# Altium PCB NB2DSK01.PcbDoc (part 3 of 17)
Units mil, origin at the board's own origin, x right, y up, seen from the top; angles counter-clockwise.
Board outline 11815 x 6500.03 mil, 8 copper layers (Top Layer, MidLayer1, MidLayer2, GND, PWR, MidLayer3, MidLayer4, Bottom Layer), stack 74.62 mil thick; 798 components, 1002 nets, 3927 pads, 3182 vias.
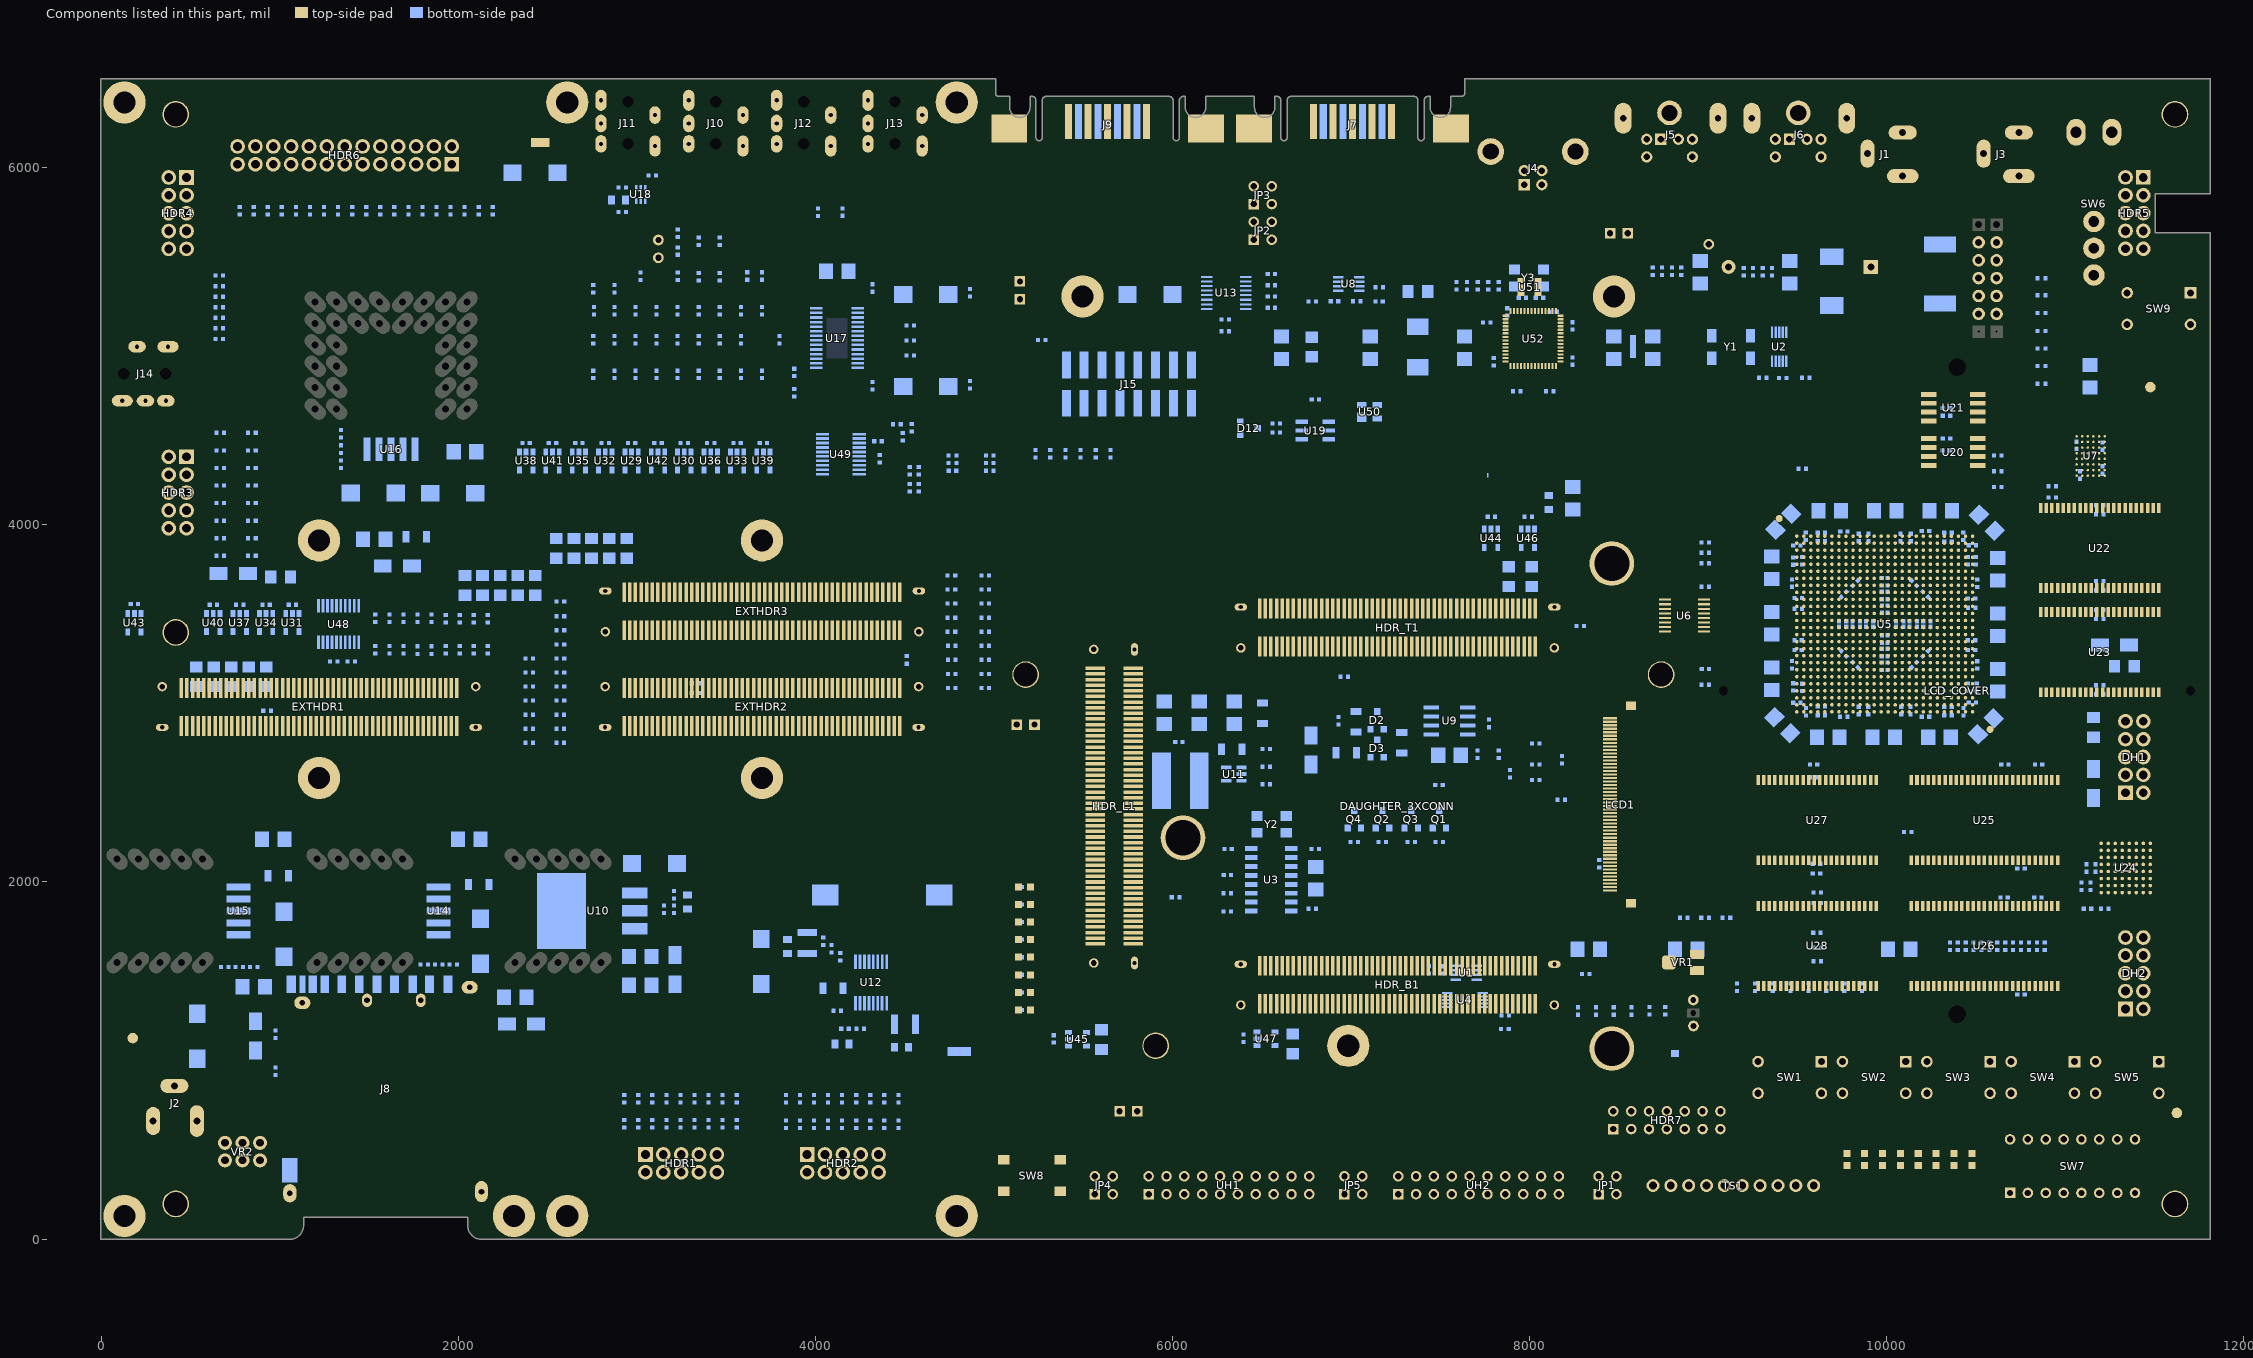
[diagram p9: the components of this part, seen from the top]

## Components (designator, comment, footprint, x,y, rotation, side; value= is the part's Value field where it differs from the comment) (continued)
R303 "1K 1%" RESC1005-STAR 10866.58,5086 r0 bottom locked (schematic designator R12)
R304 "4K7 1%" RESC1005-STAR 10866.58,4987.57 r0 bottom locked (schematic designator R8)
R305 "100R 1%" RESC1005-STAR 10866.58,5381.27 r180 bottom locked (schematic designator R9)
R306 "100R 1%" RESC1005-STAR 10866.58,5286 r180 bottom locked (schematic designator R10)
R307 "100R 1%" RESC1005-STAR 10866.58,4889.15 r0 bottom locked (schematic designator R11)
R308 "100R 1%" RESC1005-STAR 10866.58,4790.72 r0 bottom locked (schematic designator R13)
R309 "1K 1%" RESC1005-STAR 10866.58,5186 r180 bottom locked (schematic designator R14)
R311 "2K7 1%" RESC1005-STAR 7649.66,5338.57 r90 bottom (schematic designator R1_US)
R312 "5K6 1%" RESC1005-STAR 7590.54,5338.57 r270 bottom (schematic designator R2_US)
R313 "10K 1%" RESC1005-STAR 7827.02,5338.57 r270 bottom (schematic designator R8_US)
R314 "4K7 1%" RESC1005-STAR 8112.2,4748.03 r0 bottom locked (schematic designator R4_US)
R315 "27R 1%" RESC1005-STAR 9527.54,4314.95 r180 bottom locked (schematic designator R3_US)
R316 "4K7 1%" RESC1005-STAR 7927.17,4748.03 r180 bottom locked (schematic designator R7_US)
R317 "10M 1%" RESC3216 7373.87,5307.09 r180 bottom (schematic designator R9_US)
R318 "4K7 1%" RESC1005-STAR 7767.9,5338.57 r270 bottom (schematic designator R5_US)
R319 "4K7 1%" RESC1005-STAR 7708.78,5338.57 r270 bottom (schematic designator R6_US)
R320 "120R 1%" RESC1005-STAR 5231.88,4398.03 r270 bottom (schematic designator R3)
SW1 "DPNO TACTILE" IT-2175#1 9456.69,905.51 r180 top locked
SW2 "DPNO TACTILE" IT-2175#1 9929.13,905.51 r180 top locked
SW3 "DPNO TACTILE" IT-2175#1 10401.57,905.51 r180 top locked
SW4 "DPNO TACTILE" IT-2175#1 10874.02,905.51 r180 top locked
SW5 "DPNO TACTILE" IT-2175#1 11346.46,905.51 r180 top locked
SW6 "SPDT SUB" T8019L-TNQ 11160.24,6492.13 r180 top locked (schematic designator SW8)
SW7 "DIP-16 8-way Switch" DIP-16-KEY 10690.32,258.43 r0 top locked (schematic designator SW1)
SW8 "SPNO" SW_DTSM-61NT/R 5212.6,356.3 r0 top locked (schematic designator SW1)
SW9 "DPNO TACTILE" IT-2175#2 11523.62,5211.09 r180 top (schematic designator SW1)
TP1 "5V0" TestPin#1 10614.94,5381.97 r0 top (schematic designator TP2)
TP2 "32K768HZ" TestPin#2 9003.27,5571.82 r180 top locked (schematic designator TP1)
TP3 "REF CLK" TestPin#3 8917.31,1193.48 r180 top (schematic designator TP1)
TP4 "FPGA CLK" TestPin#3 8916.9,1339.03 r180 top (schematic designator TP2)
TP5 "-7V5" TestPin#1 10514.94,5581.97 r180 top (schematic designator TP1)
TP6 "9V0" TestPin#1 10514.94,5381.97 r180 top (schematic designator TP1)
TP7 "VCCX" TestPin#1 10614.94,5581.97 r0 top (schematic designator TP1)
TP8 "16V5" TestPin#1 10514.94,5481.97 r180 top (schematic designator TP1)
TP9 "1V2" TestPin#1 10614.94,5481.97 r0 top (schematic designator TP1)
TP10 "1V8" TestPin#1 10614.94,5281.97 r0 top (schematic designator TP1)
TP11 "2V5" TestPin#1 10514.94,5281.97 r180 top (schematic designator TP1)
TP12 "3V3" TestPin#1 10514.94,5181.97 r180 top (schematic designator TP1)
TP13 "MIXER LEFT" TestPin#2 3120.73,5495.67 r180 top locked (schematic designator TP1)
TP14 "MIXER RIGHT" TestPin#2 3120.73,5595.67 r180 top locked (schematic designator TP2)
TP15 "VBATT" TestPin#1 10614.94,5181.97 r0 top
TS1 "TERMINAL 10 HEADER" TS2.54X10 8690.67,300 r90 top locked
U1 "MAX1037EKA-T" SOT65P280-8 7645.59,1492.06 r180 bottom
U2 "DS1391U-33" SSOP50P490-10 9397.66,4997.47 r0 bottom locked (schematic designator U5)
U3 "ICS307-02" SOIC127P600-16 6553.15,2012.01 r270 bottom locked (schematic designator U1)
U4 "MAX5841MEUB" TSSOP50P490-10 7637.8,1339.38 r0 bottom (schematic designator U1)
U5 "XC3S1500-4FG676C" BGA100P26X26-676 9988.19,3444.88 r0 top locked (schematic designator U1)
U6 "AD7843ARU" TSOP65P638-16 8867.13,3491.5 r270 top locked (schematic designator U15)
U7 "XCF08PFS48C" BGA80P8X6-48 11141.73,4385.83 r270 top locked (schematic designator U1)
U8 "MAX3051EKA-T" SOT65P280-8 6986.05,5349.48 r180 bottom locked (schematic designator U1)
U9 "VRG-100mA-1.2V-37V-4%-75102" SOP127P600-8 7551.18,2901.77 r270 bottom locked (schematic designator U1)
U10 "LM1084IS-ADJ" TO254P1435-4 2988.68,1938.45 r270 bottom (schematic designator U1)
U11 "LM2704MF-ADJCT-ND" SOT95P284-5 6343.5,2604.33 r270 bottom locked (schematic designator U1)
U12 "MAX1831EEE" SOP63P602-16 4311.68,1437.45 r90 bottom (schematic designator U1)
U13 "MAX3232EUE" TSOP65P638-16 6301.84,5299.21 r270 bottom locked (schematic designator U9)
U14 "TPS75501KTTT" TO-263 1888.68,1838.45 r270 bottom (schematic designator U1)
U15 "TPS75501KTTT" TO-263 768.68,1838.45 r270 bottom (schematic designator U1)
U16 "TPS75501KTTT" TO-263 1623.68,4423.45 r180 bottom (schematic designator U1)
U17 "LM4849MH" TSOP65P640_HS-28 4003.94,4879.92 r90 bottom (schematic designator U1)
U18 "MAX9812L" SC70_6L 3047.24,5814.96 r180 bottom (schematic designator U1MIC)
U19 "DS2406" TSOC6 6799.27,4528.53 r270 bottom (schematic designator U1_NB)
U20 "M25P80-VMW6 8Mbit Serial Flash" SOIC8-200-BODY 10234.25,4483.07 r270 top locked (schematic designator U1)
U21 "M25P80-VMW6 8Mbit Serial Flash" SOIC8-200-BODY 10234.25,4731.1 r270 top locked (schematic designator U2)
U22 "SRAM-256Kx16" TSOP80P1176-44 11192.91,3870.08 r0 top locked (schematic designator U1)
U23 "SRAM-256Kx16" TSOP80P1176-44 11192.91,3287.4 r0 top locked (schematic designator U2)
U24 "S29GL256N11FFIV10" BGA100P8X8-64 11338.58,2078.56 r270 top locked (schematic designator U1)
U25 "SDRAM-16Mx16" TSOP80P1176-54 10547.25,2346.46 r180 top locked (schematic designator U1)
U26 "SDRAM-16Mx16" TSOP80P1176-54 10547.25,1641.73 r180 top locked (schematic designator U2)
U27 "SRAM-256Kx16" TSOP80P1176-44 9610.24,2346.46 r180 top locked (schematic designator U1)
U28 "SRAM-256Kx16" TSOP80P1176-44 9610.24,1641.73 r180 top locked (schematic designator U2)
U29 "MAX4372" SOT-23-5 2933.07,4409.45 r0 bottom (schematic designator U8)
U30 "MAX4372" SOT-23-5 3228.35,4409.45 r0 bottom (schematic designator U15)
U31 "MAX4372" SOT-23-5 1033.46,3503.94 r0 bottom (schematic designator U1)
U32 "MAX4372" SOT-23-5 2785.43,4409.45 r0 bottom (schematic designator U9)
U33 "MAX4372" SOT-23-5 3523.62,4409.45 r0 bottom (schematic designator U16)
U34 "MAX4372" SOT-23-5 885.83,3503.94 r0 bottom (schematic designator U2)
U35 "MAX4372" SOT-23-5 2637.8,4409.45 r0 bottom (schematic designator U10)
U36 "MAX4372" SOT-23-5 3375.98,4409.45 r0 bottom (schematic designator U17)
U37 "MAX4372" SOT-23-5 738.19,3503.94 r0 bottom (schematic designator U3)
U38 "MAX4372" SOT-23-5 2342.52,4409.45 r0 bottom (schematic designator U11)
U39 "MAX4372" SOT-23-5 3671.26,4409.45 r0 bottom (schematic designator U18)
U40 "MAX4372" SOT-23-5 590.55,3503.94 r0 bottom (schematic designator U4)
U41 "MAX4372" SOT-23-5 2490.16,4409.45 r0 bottom (schematic designator U12)
U42 "MAX4372" SOT-23-5 3080.71,4409.45 r0 bottom (schematic designator U19)
U43 "MAX4372" SOT-23-5 148.61,3502.9 r0 bottom (schematic designator U5)
U44 "MAX4372" SOT-23-5 7746.06,3976.38 r0 bottom (schematic designator U6)
U45 "MAX4372" SOT-23-5 5417.41,1082.08 r90 bottom (schematic designator U20)
U46 "MAX4372" SOT-23-5 7952.76,3976.38 r0 bottom (schematic designator U7)
U47 "MAX4372" SOT-23-5 6473,1085.1 r90 bottom (schematic designator U21)
U48 "MAX1229" QSOP65P600-20 1217.5,3547.24 r0 bottom (schematic designator U13)
U49 "MAX1229" QSOP65P600-20 4039.37,4283.46 r90 bottom (schematic designator U14)
U50 "MAX6315US26D1" SOT143 7103.55,4633.53 r90 bottom locked (schematic designator U16_US)
U51 "NUP2201MR6T1G" TSOP95P275-6 8000,5331.69 r90 top (schematic designator U13_US)
U52 "CY7C68001-56LFC" QFN50P800X800_HS-57 8019.68,5043.45 r180 top (schematic designator U7_US)
UH1 "2x10 HEADER" HDR2X10 5866.14,251.97 r0 top locked
UH2 "2x10 HEADER" HDR2X10 7263.78,251.97 r0 top locked
VR1 "20K linear" TRIM_3314J-1-203E 8858.27,1549.47 r180 top
VR2 "2x5K linear" POT-R0911G-A1 791.34,539.37 r180 bottom locked (schematic designator VR1)
Y1 "32.768 kHz 12.5pF" "XTAL QSC26 QSMC-200S COMBI" 9276.27,4996.46 r90 bottom
Y2 "20MHZ" XTAL-200X126-4 6555.12,2322.84 r180 bottom locked (schematic designator Y1)
Y3 "24MHZ" XTAL-200X126-4 7996.06,5382.69 r180 bottom (schematic designator Y1_US)

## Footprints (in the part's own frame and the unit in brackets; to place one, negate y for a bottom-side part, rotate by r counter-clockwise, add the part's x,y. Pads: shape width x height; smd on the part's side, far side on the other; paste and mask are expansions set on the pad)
0603LED [mm]
  rect 1x1 smd paste+0 mask+0: 1(0.85,0) 2(-0.85,0)
  silkscreen extent -1.97,-0.85 1.6,0.85, body extent -0.92,-0.53 1.09,0.53, height 0.46
53751 [mm]
  rect 0.5x2.8 smd: 1(-19.6,-2.7) 2(-19.6,2.7) 3(-18.8,-2.7) 4(-18.8,2.7) 5(-18,-2.7) 6(-18,2.7) 7(-17.2,-2.7) 8(-17.2,2.7) 9(-16.4,-2.7) 10(-16.4,2.7) 11(-15.6,-2.7) 12(-15.6,2.7) 13(-14.8,-2.7) 14(-14.8,2.7) 15(-14,-2.7) 16(-14,2.7) 17(-13.2,-2.7) 18(-13.2,2.7) 19(-12.4,-2.7) 20(-12.4,2.7) 21(-11.6,-2.7) 22(-11.6,2.7) 23(-10.8,-2.7) 24(-10.8,2.7) 25(-10,-2.7) 26(-10,2.7) 27(-9.2,-2.7) 28(-9.2,2.7) 29(-8.4,-2.7) 30(-8.4,2.7) 31(-7.6,-2.7) 32(-7.6,2.7) 33(-6.8,-2.7) 34(-6.8,2.7) 35(-6,-2.7) 36(-6,2.7) 37(-5.2,-2.7) 38(-5.2,2.7) 39(-4.4,-2.7) 40(-4.4,2.7) 41(-3.6,-2.7) 42(-3.6,2.7) 43(-2.8,-2.7) 44(-2.8,2.7) 45(-2,-2.7) 46(-2,2.7) 47(-1.2,-2.7) 48(-1.2,2.7) 49(-0.4,-2.7) 50(-0.4,2.7) 51(0.4,-2.7) 52(0.4,2.7) 53(1.2,-2.7) 54(1.2,2.7) 55(2,-2.7) 56(2,2.7) 57(2.8,-2.7) 58(2.8,2.7) 59(3.6,-2.7) 60(3.6,2.7) 61(4.4,-2.7) 62(4.4,2.7) 63(5.2,-2.7) 64(5.2,2.7) 65(6,-2.7) 66(6,2.7) 67(6.8,-2.7) 68(6.8,2.7) 69(7.6,-2.7) 70(7.6,2.7) 71(8.4,-2.7) 72(8.4,2.7) 73(9.2,-2.7) 74(9.2,2.7) 75(10,-2.7) 76(10,2.7) 77(10.8,-2.7) 78(10.8,2.7) 79(11.6,-2.7) 80(11.6,2.7) 81(12.4,-2.7) 82(12.4,2.7) 83(13.2,-2.7) 84(13.2,2.7) 85(14,-2.7) 86(14,2.7) 87(14.8,-2.7) 88(14.8,2.7) 89(15.6,-2.7) 90(15.6,2.7) 91(16.4,-2.7) 92(16.4,2.7) 93(17.2,-2.7) 94(17.2,2.7) 95(18,-2.7) 96(18,2.7) 97(18.8,-2.7) 98(18.8,2.7) 99(19.6,-2.7) 100(19.6,2.7)
  round 1.35 hole 0.8: MH1(-22.283,-2.9) MH3(22.317,-2.9)
  oval 1.8x1 hole 0.6 slot 1.4 at 0 deg: MH2(-22.283,2.9) MH4(22.317,2.9)
  silkscreen extent -30,-4.77 30.05,4.5, body extent -30.33,-4.4 30.37,4.4, height 11.7
070221XE009GX14BU#1 [mm]
  rect 1x5 smd mask+0: 1(5.55,0) 2(2.775,0) 3(0,0) 4(-2.775,0) 5(-5.55,0)
  rect 1x5 smd far side mask+0: 6(4.163,0) 7(1.388,0) 8(-1.388,0) 9(-4.163,0)
  rect 5.08x4 smd mask+0: 10(14,-1) 11(-14,-1)
  silkscreen extent -16.5,-4.9 16.5,8.01, body extent -15.41,-0.4 15.41,14.1, height 6.25
070221XE009GX14BU#2 [mm]
  rect 1x5 smd mask+0: 1(5.55,0) 2(2.775,0) 3(0,0) 4(-2.775,0) 5(-5.55,0)
  rect 1x5 smd far side: 6(4.163,0) 7(1.388,0) 8(-1.388,0) 9(-4.163,0)
  rect 5.08x4 smd mask+0.051: 10(14,-1) 11(-14,-1)
  silkscreen extent -16.5,-4.9 16.5,8.01, body extent -15.41,-0.4 15.41,14.1, height 6.25
440119 [mm] "Connector; USB1.1, Type B, Thru-Hole; 4 Position; Right Angle"
  rect 1.6x1.6 hole 0.9: 1(-1,1.25)
  round 1.6 hole 0.9: 2(-1,-1.25) 3(1,-1.25) 4(1,1.25)
  round 3.8 hole 2.3: 5(3.71,6.02) 6(3.71,-6.02)
  silkscreen extent -2.41,-8.25 13.99,8.24, body extent -1.44,-6.75 13.28,8.15, height 8.15
918510X323#1 [mil] "Connector; IDC, Low Profile Male Header, Thru-Hole; 10 Position; Right Angle; Pitch 2.54 mm; Body 20.32 x 8.9 x 9.2 mm (LxWxH)"
  rect 82x82 hole 49.21: 1(-200,-100)
  round 82 hole 49.21: 2(-200,0) 3(-100,-100) 4(-100,0) 5(0,-100) 6(0,0) 7(100,-100) 8(100,0) 9(200,-100) 10(200,0)
  silkscreen extent -400,0 400,372, body extent -406,-123 406,374, height 315
918510X323#2 [mil] "Connector; IDC, Low Profile Male Header, Thru-Hole; 10 Position; Right Angle; Pitch 2.54 mm; Body 20.32 x 8.9 x 9.2 mm (LxWxH)"
  rect 82x82 hole 49.21: 1(200,100)
  round 82 hole 49.21: 2(200,0) 3(100,100) 4(100,0) 5(0,100) 6(0,0) 7(-100,100) 8(-100,0) 9(-200,100) 10(-200,0)
  silkscreen extent -400,-372 400,0
918510X323#3 [mil] "Connector; IDC, Low Profile Male Header, Thru-Hole; 10 Position; Right Angle; Pitch 2.54 mm; Body 20.32 x 8.9 x 9.2 mm (LxWxH)"
  rect 82x82 hole 49.21: 1(200,0)
  round 82 hole 49.21: 2(200,-100) 3(100,0) 4(100,-100) 5(0,0) 6(0,-100) 7(-100,0) 8(-100,-100) 9(-200,0) 10(-200,-100)
  silkscreen extent -400,0 400,372, body extent -406,-123 406,374, height 315
BGA80P8X6-48 [mm] "48-Ball Chip Scale Ball Grid Array 0.8mm Pitch (FS48)"
  round 0.35 smd: A1(-2.8,-2) A2(-2.8,-1.2) A3(-2.8,-0.4) A4(-2.8,0.4) A5(-2.8,1.2) A6(-2.8,2) B1(-2,-2) B2(-2,-1.2) B3(-2,-0.4) B4(-2,0.4) B5(-2,1.2) B6(-2,2) C1(-1.2,-2) C2(-1.2,-1.2) C3(-1.2,-0.4) C4(-1.2,0.4) C5(-1.2,1.2) C6(-1.2,2) D1(-0.4,-2) D2(-0.4,-1.2) D3(-0.4,-0.4) D4(-0.4,0.4) D5(-0.4,1.2) D6(-0.4,2) E1(0.4,-2) E2(0.4,-1.2) E3(0.4,-0.4) E4(0.4,0.4) E5(0.4,1.2) E6(0.4,2) F1(1.2,-2) F2(1.2,-1.2) F3(1.2,-0.4) F4(1.2,0.4) F5(1.2,1.2) F6(1.2,2) G1(2,-2) G2(2,-1.2) G3(2,-0.4) G4(2,0.4) G5(2,1.2) G6(2,2) H1(2.8,-2) H2(2.8,-1.2) H3(2.8,-0.4) H4(2.8,0.4) H5(2.8,1.2) H6(2.8,2)
  silkscreen extent -4.5,-4.78 4.5,4, body extent -4.51,-3.92 4.42,3.97, height 1
BGA100P8X8-64 [mm] "AMD 64-Ball Fortfied Ball grid Array (FBGA)"
  round 0.5 smd: A1(-3.5,-3.5) A2(-3.5,-2.5) A3(-3.5,-1.5) A4(-3.5,-0.5) A5(-3.5,0.5) A6(-3.5,1.5) A7(-3.5,2.5) A8(-3.5,3.5) B1(-2.5,-3.5) B2(-2.5,-2.5) B3(-2.5,-1.5) B4(-2.5,-0.5) B5(-2.5,0.5) B6(-2.5,1.5) B7(-2.5,2.5) B8(-2.5,3.5) C1(-1.5,-3.5) C2(-1.5,-2.5) C3(-1.5,-1.5) C4(-1.5,-0.5) C5(-1.5,0.5) C6(-1.5,1.5) C7(-1.5,2.5) C8(-1.5,3.5) D1(-0.5,-3.5) D2(-0.5,-2.5) D3(-0.5,-1.5) D4(-0.5,-0.5) D5(-0.5,0.5) D6(-0.5,1.5) D7(-0.5,2.5) D8(-0.5,3.5) E1(0.5,-3.5) E2(0.5,-2.5) E3(0.5,-1.5) E4(0.5,-0.5) E5(0.5,0.5) E6(0.5,1.5) E7(0.5,2.5) E8(0.5,3.5) F1(1.5,-3.5) F2(1.5,-2.5) F3(1.5,-1.5) F4(1.5,-0.5) F5(1.5,0.5) F6(1.5,1.5) F7(1.5,2.5) F8(1.5,3.5) G1(2.5,-3.5) G2(2.5,-2.5) G3(2.5,-1.5) G4(2.5,-0.5) G5(2.5,0.5) G6(2.5,1.5) G7(2.5,2.5) G8(2.5,3.5) H1(3.5,-3.5) H2(3.5,-2.5) H3(3.5,-1.5) H4(3.5,-0.5) H5(3.5,0.5) H6(3.5,1.5) H7(3.5,2.5) H8(3.5,3.5)
  silkscreen extent -6.5,-6.32 6.5,5.5, body extent -6.35,-5.4 6.41,5.36, height 1
BGA100P26X26-676 [mm]
  round 0.5 smd: A1(-12.5,12.5) A2(-11.5,12.5) A3(-10.5,12.5) A4(-9.5,12.5) A5(-8.5,12.5) A6(-7.5,12.5) A7(-6.5,12.5) A8(-5.5,12.5) A9(-4.5,12.5) A10(-3.5,12.5) A11(-2.5,12.5) A12(-1.5,12.5) A13(-0.5,12.5) A14(0.5,12.5) A15(1.5,12.5) A16(2.5,12.5) A17(3.5,12.5) A18(4.5,12.5) A19(5.5,12.5) A20(6.5,12.5) A21(7.5,12.5) A22(8.5,12.5) A23(9.5,12.5) A24(10.5,12.5) A25(11.5,12.5) A26(12.5,12.5) AA1(-12.5,-7.5) AA2(-11.5,-7.5) AA3(-10.5,-7.5) AA4(-9.5,-7.5) AA5(-8.5,-7.5) AA6(-7.5,-7.5) AA7(-6.5,-7.5) AA8(-5.5,-7.5) AA9(-4.5,-7.5) AA10(-3.5,-7.5) AA11(-2.5,-7.5) AA12(-1.5,-7.5) AA13(-0.5,-7.5) AA14(0.5,-7.5) AA15(1.5,-7.5) AA16(2.5,-7.5) AA17(3.5,-7.5) AA18(4.5,-7.5) AA19(5.5,-7.5) AA20(6.5,-7.5) AA21(7.5,-7.5) AA22(8.5,-7.5) AA23(9.5,-7.5) AA24(10.5,-7.5) AA25(11.5,-7.5) AA26(12.5,-7.5) AB1(-12.5,-8.5) AB2(-11.5,-8.5) AB3(-10.5,-8.5) AB4(-9.5,-8.5) AB5(-8.5,-8.5) AB6(-7.5,-8.5) AB7(-6.5,-8.5) AB8(-5.5,-8.5) AB9(-4.5,-8.5) AB10(-3.5,-8.5) AB11(-2.5,-8.5) AB12(-1.5,-8.5) AB13(-0.5,-8.5) AB14(0.5,-8.5) AB15(1.5,-8.5) AB16(2.5,-8.5) AB17(3.5,-8.5) AB18(4.5,-8.5) AB19(5.5,-8.5) AB20(6.5,-8.5) AB21(7.5,-8.5) AB22(8.5,-8.5) AB23(9.5,-8.5) AB24(10.5,-8.5) AB25(11.5,-8.5) AB26(12.5,-8.5) AC1(-12.5,-9.5) AC2(-11.5,-9.5) AC3(-10.5,-9.5) AC4(-9.5,-9.5) AC5(-8.5,-9.5) AC6(-7.5,-9.5) AC7(-6.5,-9.5) AC8(-5.5,-9.5) AC9(-4.5,-9.5) AC10(-3.5,-9.5) AC11(-2.5,-9.5) AC12(-1.5,-9.5) AC13(-0.5,-9.5) AC14(0.5,-9.5) AC15(1.5,-9.5) AC16(2.5,-9.5) AC17(3.5,-9.5) AC18(4.5,-9.5) AC19(5.5,-9.5) AC20(6.5,-9.5) AC21(7.5,-9.5) AC22(8.5,-9.5) AC23(9.5,-9.5) AC24(10.5,-9.5) AC25(11.5,-9.5) AC26(12.5,-9.5) AD1(-12.5,-10.5) AD2(-11.5,-10.5) AD3(-10.5,-10.5) AD4(-9.5,-10.5) AD5(-8.5,-10.5) AD6(-7.5,-10.5) AD7(-6.5,-10.5) AD8(-5.5,-10.5) AD9(-4.5,-10.5) AD10(-3.5,-10.5) AD11(-2.5,-10.5) AD12(-1.5,-10.5) AD13(-0.5,-10.5) AD14(0.5,-10.5) AD15(1.5,-10.5) AD16(2.5,-10.5) AD17(3.5,-10.5) AD18(4.5,-10.5) AD19(5.5,-10.5) AD20(6.5,-10.5) AD21(7.5,-10.5) AD22(8.5,-10.5) AD23(9.5,-10.5) AD24(10.5,-10.5) AD25(11.5,-10.5) AD26(12.5,-10.5) AE1(-12.5,-11.5) AE2(-11.5,-11.5) AE3(-10.5,-11.5) AE4(-9.5,-11.5) AE5(-8.5,-11.5) AE6(-7.5,-11.5) AE7(-6.5,-11.5) AE8(-5.5,-11.5) AE9(-4.5,-11.5) AE10(-3.5,-11.5) AE11(-2.5,-11.5) AE12(-1.5,-11.5) AE13(-0.5,-11.5) AE14(0.5,-11.5) AE15(1.5,-11.5) AE16(2.5,-11.5) AE17(3.5,-11.5) AE18(4.5,-11.5) AE19(5.5,-11.5) AE20(6.5,-11.5) AE21(7.5,-11.5) AE22(8.5,-11.5) AE23(9.5,-11.5) AE24(10.5,-11.5) AE25(11.5,-11.5) AE26(12.5,-11.5) AF1(-12.5,-12.5) AF2(-11.5,-12.5) AF3(-10.5,-12.5) AF4(-9.5,-12.5) AF5(-8.5,-12.5) AF6(-7.5,-12.5) AF7(-6.5,-12.5) AF8(-5.5,-12.5) AF9(-4.5,-12.5) AF10(-3.5,-12.5) AF11(-2.5,-12.5) AF12(-1.5,-12.5) AF13(-0.5,-12.5) AF14(0.5,-12.5) AF15(1.5,-12.5) AF16(2.5,-12.5) AF17(3.5,-12.5) AF18(4.5,-12.5) AF19(5.5,-12.5) AF20(6.5,-12.5) AF21(7.5,-12.5) AF22(8.5,-12.5) AF23(9.5,-12.5) AF24(10.5,-12.5) AF25(11.5,-12.5) AF26(12.5,-12.5) B1(-12.5,11.5) B2(-11.5,11.5) B3(-10.5,11.5) B4(-9.5,11.5) B5(-8.5,11.5) B6(-7.5,11.5) B7(-6.5,11.5) B8(-5.5,11.5) B9(-4.5,11.5) B10(-3.5,11.5) B11(-2.5,11.5) B12(-1.5,11.5) B13(-0.5,11.5) B14(0.5,11.5) B15(1.5,11.5) B16(2.5,11.5) B17(3.5,11.5) B18(4.5,11.5) B19(5.5,11.5) B20(6.5,11.5) B21(7.5,11.5) B22(8.5,11.5) B23(9.5,11.5) B24(10.5,11.5) B25(11.5,11.5) B26(12.5,11.5) C1(-12.5,10.5) C2(-11.5,10.5) C3(-10.5,10.5) C4(-9.5,10.5) C5(-8.5,10.5) C6(-7.5,10.5) C7(-6.5,10.5) C8(-5.5,10.5) C9(-4.5,10.5) C10(-3.5,10.5) C11(-2.5,10.5) C12(-1.5,10.5) C13(-0.5,10.5) C14(0.5,10.5) C15(1.5,10.5) C16(2.5,10.5) C17(3.5,10.5) C18(4.5,10.5) C19(5.5,10.5) C20(6.5,10.5) C21(7.5,10.5) C22(8.5,10.5) C23(9.5,10.5) C24(10.5,10.5) C25(11.5,10.5) C26(12.5,10.5) D1(-12.5,9.5) D2(-11.5,9.5) D3(-10.5,9.5) D4(-9.5,9.5) D5(-8.5,9.5) D6(-7.5,9.5) D7(-6.5,9.5) D8(-5.5,9.5) D9(-4.5,9.5) D10(-3.5,9.5) D11(-2.5,9.5) D12(-1.5,9.5) D13(-0.5,9.5) D14(0.5,9.5) D15(1.5,9.5) D16(2.5,9.5) D17(3.5,9.5) D18(4.5,9.5) D19(5.5,9.5) D20(6.5,9.5) D21(7.5,9.5) D22(8.5,9.5) D23(9.5,9.5) D24(10.5,9.5) D25(11.5,9.5) D26(12.5,9.5) E1(-12.5,8.5) E2(-11.5,8.5) E3(-10.5,8.5) E4(-9.5,8.5) E5(-8.5,8.5) E6(-7.5,8.5) E7(-6.5,8.5) E8(-5.5,8.5) E9(-4.5,8.5) E10(-3.5,8.5) E11(-2.5,8.5) E12(-1.5,8.5) E13(-0.5,8.5) E14(0.5,8.5) E15(1.5,8.5) E16(2.5,8.5) E17(3.5,8.5) E18(4.5,8.5) E19(5.5,8.5) E20(6.5,8.5) E21(7.5,8.5) E22(8.5,8.5) E23(9.5,8.5) E24(10.5,8.5) E25(11.5,8.5) E26(12.5,8.5) F1(-12.5,7.5) F2(-11.5,7.5) F3(-10.5,7.5) F4(-9.5,7.5) F5(-8.5,7.5) F6(-7.5,7.5) F7(-6.5,7.5) F8(-5.5,7.5) F9(-4.5,7.5) F10(-3.5,7.5) F11(-2.5,7.5) F12(-1.5,7.5) F13(-0.5,7.5) F14(0.5,7.5) F15(1.5,7.5) F16(2.5,7.5) F17(3.5,7.5) F18(4.5,7.5) F19(5.5,7.5) F20(6.5,7.5) F21(7.5,7.5) F22(8.5,7.5) F23(9.5,7.5) F24(10.5,7.5) F25(11.5,7.5) F26(12.5,7.5) G1(-12.5,6.5) G2(-11.5,6.5) G3(-10.5,6.5) G4(-9.5,6.5) G5(-8.5,6.5) G6(-7.5,6.5) G7(-6.5,6.5) G8(-5.5,6.5) G9(-4.5,6.5) G10(-3.5,6.5) G11(-2.5,6.5) G12(-1.5,6.5) G13(-0.5,6.5) G14(0.5,6.5) G15(1.5,6.5) G16(2.5,6.5) G17(3.5,6.5) G18(4.5,6.5) G19(5.5,6.5) G20(6.5,6.5) G21(7.5,6.5) G22(8.5,6.5) G23(9.5,6.5) G24(10.5,6.5) G25(11.5,6.5) G26(12.5,6.5) H1(-12.5,5.5) H2(-11.5,5.5) H3(-10.5,5.5) H4(-9.5,5.5) H5(-8.5,5.5) H6(-7.5,5.5) H7(-6.5,5.5) H8(-5.5,5.5) H9(-4.5,5.5) H10(-3.5,5.5) H11(-2.5,5.5) H12(-1.5,5.5) H13(-0.5,5.5) H14(0.5,5.5) H15(1.5,5.5) H16(2.5,5.5) H17(3.5,5.5) H18(4.5,5.5) H19(5.5,5.5) H20(6.5,5.5) H21(7.5,5.5) H22(8.5,5.5) H23(9.5,5.5) H24(10.5,5.5) H25(11.5,5.5) H26(12.5,5.5) J1(-12.5,4.5) J2(-11.5,4.5) J3(-10.5,4.5) J4(-9.5,4.5) J5(-8.5,4.5) J6(-7.5,4.5) J7(-6.5,4.5) J8(-5.5,4.5) J9(-4.5,4.5) J10(-3.5,4.5) J11(-2.5,4.5) J12(-1.5,4.5) J13(-0.5,4.5) J14(0.5,4.5) J15(1.5,4.5) J16(2.5,4.5) J17(3.5,4.5) J18(4.5,4.5) J19(5.5,4.5) J20(6.5,4.5) J21(7.5,4.5) J22(8.5,4.5) J23(9.5,4.5) J24(10.5,4.5) J25(11.5,4.5) J26(12.5,4.5) K1(-12.5,3.5) K2(-11.5,3.5) K3(-10.5,3.5) K4(-9.5,3.5) K5(-8.5,3.5) K6(-7.5,3.5) K7(-6.5,3.5) K8(-5.5,3.5) K9(-4.5,3.5) K10(-3.5,3.5) K11(-2.5,3.5) K12(-1.5,3.5) K13(-0.5,3.5) K14(0.5,3.5) K15(1.5,3.5) K16(2.5,3.5) K17(3.5,3.5) K18(4.5,3.5) K19(5.5,3.5) K20(6.5,3.5) K21(7.5,3.5) K22(8.5,3.5) K23(9.5,3.5) K24(10.5,3.5) K25(11.5,3.5) K26(12.5,3.5) L1(-12.5,2.5) L2(-11.5,2.5) L3(-10.5,2.5) L4(-9.5,2.5) L5(-8.5,2.5) L6(-7.5,2.5) L7(-6.5,2.5) L8(-5.5,2.5) L9(-4.5,2.5) L10(-3.5,2.5) L11(-2.5,2.5) L12(-1.5,2.5) L13(-0.5,2.5) L14(0.5,2.5) L15(1.5,2.5) L16(2.5,2.5) L17(3.5,2.5) L18(4.5,2.5) L19(5.5,2.5) L20(6.5,2.5) L21(7.5,2.5) L22(8.5,2.5) L23(9.5,2.5) L24(10.5,2.5) L25(11.5,2.5) L26(12.5,2.5) M1(-12.5,1.5) M2(-11.5,1.5) M3(-10.5,1.5) M4(-9.5,1.5) M5(-8.5,1.5) M6(-7.5,1.5) M7(-6.5,1.5) M8(-5.5,1.5) M9(-4.5,1.5) M10(-3.5,1.5) M11(-2.5,1.5) M12(-1.5,1.5) M13(-0.5,1.5) M14(0.5,1.5) M15(1.5,1.5) M16(2.5,1.5) M17(3.5,1.5) M18(4.5,1.5) M19(5.5,1.5) M20(6.5,1.5) M21(7.5,1.5) M22(8.5,1.5) M23(9.5,1.5) M24(10.5,1.5) M25(11.5,1.5) M26(12.5,1.5) N1(-12.5,0.5) N2(-11.5,0.5) N3(-10.5,0.5) N4(-9.5,0.5) N5(-8.5,0.5) N6(-7.5,0.5) N7(-6.5,0.5) N8(-5.5,0.5) N9(-4.5,0.5) N10(-3.5,0.5) N11(-2.5,0.5) N12(-1.5,0.5) N13(-0.5,0.5) N14(0.5,0.5) N15(1.5,0.5) N16(2.5,0.5) N17(3.5,0.5) N18(4.5,0.5) N19(5.5,0.5) N20(6.5,0.5) N21(7.5,0.5) N22(8.5,0.5) N23(9.5,0.5) N24(10.5,0.5) N25(11.5,0.5) N26(12.5,0.5) P1(-12.5,-0.5) P2(-11.5,-0.5) P3(-10.5,-0.5) P4(-9.5,-0.5) P5(-8.5,-0.5) P6(-7.5,-0.5) P7(-6.5,-0.5) P8(-5.5,-0.5) P9(-4.5,-0.5) P10(-3.5,-0.5) P11(-2.5,-0.5) P12(-1.5,-0.5) P13(-0.5,-0.5) P14(0.5,-0.5) P15(1.5,-0.5) P16(2.5,-0.5) P17(3.5,-0.5) P18(4.5,-0.5) P19(5.5,-0.5) P20(6.5,-0.5) P21(7.5,-0.5) P22(8.5,-0.5) P23(9.5,-0.5) P24(10.5,-0.5) P25(11.5,-0.5) P26(12.5,-0.5) R1(-12.5,-1.5) R2(-11.5,-1.5) R3(-10.5,-1.5) R4(-9.5,-1.5) R5(-8.5,-1.5) R6(-7.5,-1.5) R7(-6.5,-1.5) R8(-5.5,-1.5) R9(-4.5,-1.5) R10(-3.5,-1.5) R11(-2.5,-1.5) R12(-1.5,-1.5) R13(-0.5,-1.5) R14(0.5,-1.5) R15(1.5,-1.5) R16(2.5,-1.5) R17(3.5,-1.5) R18(4.5,-1.5) R19(5.5,-1.5) R20(6.5,-1.5) R21(7.5,-1.5) R22(8.5,-1.5) R23(9.5,-1.5) R24(10.5,-1.5) R25(11.5,-1.5) R26(12.5,-1.5) T1(-12.5,-2.5) T2(-11.5,-2.5) T3(-10.5,-2.5) T4(-9.5,-2.5) T5(-8.5,-2.5) T6(-7.5,-2.5) T7(-6.5,-2.5) T8(-5.5,-2.5) T9(-4.5,-2.5) T10(-3.5,-2.5) T11(-2.5,-2.5) T12(-1.5,-2.5) T13(-0.5,-2.5) T14(0.5,-2.5) T15(1.5,-2.5) T16(2.5,-2.5) T17(3.5,-2.5) T18(4.5,-2.5) T19(5.5,-2.5) T20(6.5,-2.5) T21(7.5,-2.5) T22(8.5,-2.5) T23(9.5,-2.5) T24(10.5,-2.5) T25(11.5,-2.5) T26(12.5,-2.5) U1(-12.5,-3.5) U2(-11.5,-3.5) U3(-10.5,-3.5) U4(-9.5,-3.5) U5(-8.5,-3.5) U6(-7.5,-3.5) U7(-6.5,-3.5) U8(-5.5,-3.5) U9(-4.5,-3.5) U10(-3.5,-3.5) U11(-2.5,-3.5) U12(-1.5,-3.5) U13(-0.5,-3.5) U14(0.5,-3.5) U15(1.5,-3.5) U16(2.5,-3.5) U17(3.5,-3.5) U18(4.5,-3.5) U19(5.5,-3.5) U20(6.5,-3.5) U21(7.5,-3.5) U22(8.5,-3.5) U23(9.5,-3.5) U24(10.5,-3.5) U25(11.5,-3.5) U26(12.5,-3.5) V1(-12.5,-4.5) V2(-11.5,-4.5) V3(-10.5,-4.5) V4(-9.5,-4.5) V5(-8.5,-4.5) V6(-7.5,-4.5) V7(-6.5,-4.5) V8(-5.5,-4.5) V9(-4.5,-4.5) V10(-3.5,-4.5) V11(-2.5,-4.5) V12(-1.5,-4.5) V13(-0.5,-4.5) V14(0.5,-4.5) V15(1.5,-4.5) V16(2.5,-4.5) V17(3.5,-4.5) V18(4.5,-4.5) V19(5.5,-4.5) V20(6.5,-4.5) V21(7.5,-4.5) V22(8.5,-4.5) V23(9.5,-4.5) V24(10.5,-4.5) V25(11.5,-4.5) V26(12.5,-4.5) W1(-12.5,-5.5) W2(-11.5,-5.5) W3(-10.5,-5.5) W4(-9.5,-5.5) W5(-8.5,-5.5) W6(-7.5,-5.5) W7(-6.5,-5.5) W8(-5.5,-5.5) W9(-4.5,-5.5) W10(-3.5,-5.5) W11(-2.5,-5.5) W12(-1.5,-5.5) W13(-0.5,-5.5) W14(0.5,-5.5) W15(1.5,-5.5) W16(2.5,-5.5) W17(3.5,-5.5) W18(4.5,-5.5) W19(5.5,-5.5) W20(6.5,-5.5) W21(7.5,-5.5) W22(8.5,-5.5) W23(9.5,-5.5) W24(10.5,-5.5) W25(11.5,-5.5) W26(12.5,-5.5) Y1(-12.5,-6.5) Y2(-11.5,-6.5) Y3(-10.5,-6.5) Y4(-9.5,-6.5) Y5(-8.5,-6.5) Y6(-7.5,-6.5) Y7(-6.5,-6.5) Y8(-5.5,-6.5) Y9(-4.5,-6.5) Y10(-3.5,-6.5) Y11(-2.5,-6.5) Y12(-1.5,-6.5) Y13(-0.5,-6.5) Y14(0.5,-6.5) Y15(1.5,-6.5) Y16(2.5,-6.5) Y17(3.5,-6.5) Y18(4.5,-6.5) Y19(5.5,-6.5) Y20(6.5,-6.5) Y21(7.5,-6.5) Y22(8.5,-6.5) Y23(9.5,-6.5) Y24(10.5,-6.5) Y25(11.5,-6.5) Y26(12.5,-6.5)
  round 1 on Mech7 paste-0.55 mask+1: FID1(-15,15) FID1(15,-15)
  round 1 smd paste-0.55 mask+0.635: FID1(-15,15) FID1(15,-15)
  Top Layer keep-out circle w0.2: c-15,15 r1
  Top Layer keep-out circle w0.2: c15,-15 r1
  silkscreen extent -14.77,-13.5 13.5,13.5, body extent -13.55,-13.45 13.45,13.55, height 2.6
CAPC1005-STAR [mm] "Chip Capacitor 1005"
  rect 0.6x0.6 smd: 1(-0.525,0) 2(0.525,0)
  silkscreen extent -0.05,-0.38 0.05,0.38, body extent -0.57,-0.3 0.57,0.3, height 0.2
CAPC2012-STAR [mm] "0805 Capacitor SMD - Startronics"
  rect 1x1.25 smd: 1(-1,0) 2(1,0)
  silkscreen extent -0.4,-1 0.4,1, body extent -1.32,-0.69 1.23,0.67, height 0.5
CAPC3216-STAR [mm] "Capacitor 1206 (3216) for Startronics"
  rect 1x1.6 smd: 1(-1.45,0) 2(1.45,0)
  silkscreen extent -0.62,-1.1 0.62,1.1, body extent -1.64,-0.89 1.63,0.86, height 0.9
CAPC3225-STAR [mm] "1210 Capacitor SMD - Startronics"
  rect 1x2.75 smd: 1(-1.5,0) 2(1.5,0)
  silkscreen extent -0.7,-1.5 0.7,1.5, body extent -1.94,-1.2 1.89,1.29, height 1.5
CAPC3528-STAR [mm] "Capacitor 3.5x2.8mm (B-Case)"
  rect 2x2.2 smd: 1(-1.6,0) 2(1.6,0)
  silkscreen extent -3,-1.7 3.05,1.7, body extent -1.79,-1.54 1.8,1.54, height 1
CAPC7343-STAR [mm] "Capcacitor SMD 7.3 x 4.3mm (D-Case)"
  rect 2.6x2.4 smd: 1(-3.202,0.007) 2(3.198,0.007)
  silkscreen extent -5.33,-2.39 5.08,2.41, body extent -3.5,-2.03 3.51,2.04, height 1.75
CAPM7163 [mm]
  rect 2.35x3.1 smd: 1(-2.875,0) 2(2.875,0)
  silkscreen extent -3.5,-3.15 3.5,3.15, body extent -3.1,-2.64 3.2,2.81, height 1.5
CELL_HOLDER [mm] "Lithium Battery Holder for CR2032 3V Cell"
  round 2 hole 1: 1(12.275,0)
  rect 2x2 hole 1: 2(-7.95,0)
  Top Layer keep-out region: -6.475,-3.6 -3.95,-3.6 -3.95,3.6 -6.475,3.6
  Top Layer keep-out region: -3.95,1.525 -3.95,3.6 -8.1,3.6 -8.1,1.525
  Top Layer keep-out region: -8.1,-1.525 -8.1,-3.6 -3.95,-3.6 -3.95,-1.525
  Top Layer keep-out region: 12.3,1.525 12.3,3.6 9.575,3.6 9.575,1.525
  Top Layer keep-out region: 9.575,-1.525 9.575,-3.6 12.3,-3.6 12.3,-1.525
  Top Layer keep-out region: 10.8,3.6 9.575,3.6 9.575,-3.6 10.8,-3.6
  silkscreen extent -10.6,-10.6 13.47,10.6, body extent -10.62,-10.59 13.17,10.63, height 10
DAUGHTER_BOARD_2XCONN [mil] "Outline of 2-Connector Daughter Board"
DAUGHTER_BOARD_3XCONN [mm] "Outline of 3-Connector Daughter Board"
  round 6.35 hole 5 paste+0 mask+0: LPA(37.492,68.6) LPB(-23.508,29.6) LPC(37.492,-0.4)
  Top Layer region: -41.203,105.291 -41.203,110.106 -43.134,110.106 -43.134,105.291
  Top Layer region: -31.022,112.031 -41.203,112.031 -41.203,110.1 -31.022,110.1
  Top Layer region: 43.134,105.291 43.134,110.106 41.203,110.106 41.203,105.291
  Top Layer region: 31.022,110.1 41.203,110.1 41.203,112.031 31.022,112.031
  Top Layer region: -43.131,1.506 -43.131,-3.309 -41.2,-3.309 -41.2,1.506
  Top Layer region: -31.019,-3.315 -41.2,-3.315 -41.2,-5.246 -31.019,-5.246
  Top Layer lines w0.5: -41.45,109.85 cw(c-40.95,109.85) -40.95,110.35 ; -41.447,-3.066 ccw(c-40.947,-3.066) -40.947,-3.566 ; 40.95,110.35 cw(c40.95,109.85) 41.45,109.85
  Top Layer lines w1.9: -42.182,110.033 cw(c-41.133,110.033) -41.133,111.082 ; -42.18,-3.248 ccw(c-41.13,-3.248) -41.13,-4.298 ; 41.133,111.082 cw(c41.133,110.033) 42.182,110.033
  silkscreen extent -43.13,-5.24 43.13,112.03
DIOM5027 [mm]
  rect 2.55x1.85 smd: 1(-2.075,0) 2(2.075,0)
  silkscreen extent -3.75,-1.33 4.05,1.33, body extent -2.36,-0.91 2.46,0.92, height 1.3
DIOM8059 [mm] "DO-214-AB/SMC; 2 C-Bend Leads; Body 7.9 x 5.9 mm, inc. leads (LxW)"
  rect 2.4x3.3 smd: 1(-3.475,0) 2(3.475,0)
  silkscreen extent -5.07,-2.05 5.43,2.05, body extent -3.29,-1.56 3.92,1.57, height 1.3
DIP-16-KEY [mm] "DIP; 16 Leads; Row Spacing 7.62 mm; Pitch 2.54 mm"
  rect 1.5x1.5 hole 0.9: 1(0,0)
  round 1.5 hole 0.9: 2(2.54,0) 3(5.08,0) 4(7.62,0) 5(10.16,0) 6(12.7,0) 7(15.24,0) 8(17.78,0) 9(17.78,7.62) 10(15.24,7.62) 11(12.7,7.62) 12(10.16,7.62) 13(7.62,7.62) 14(5.08,7.62) 15(2.54,7.62) 16(0,7.62)
  silkscreen extent -2.05,-1.59 19.83,9.2, body extent -2.01,-1.76 19.88,9.49, height 6
"FIDUCIAL ROUND" [mm] "FIDUCIAL ROUND"
  round 1.5 all layers, no hole paste+0 mask+1.1: 0(0,0)
  Top Layer circle w0.127: c0,0 r1.778
  Bottom Layer circle w0.127: c0,0 r1.778
  Keep-Out Layer circle w0.1: c0,0 r1.9
HDR1X2 [mm]
  rect 1.5x1.5 hole 0.9: 1(-0.01,0.007) 2(2.53,0.007)
  silkscreen extent -1.28,-1.26 3.8,1.28, body extent -1.03,-0.98 3.47,1.02, height 7
HDR2X2 [mm]
  rect 1.5x1.5 hole 0.9: 1(0,0)
  round 1.5 hole 0.9: 2(0,2.54) 3(2.54,0) 4(2.54,2.54)
  silkscreen extent -1.27,-1.27 3.81,3.81, body extent -1.19,-1.15 3.67,3.73, height 9
HDR2X7 [mm]
  rect 1.5x1.5 hole 0.9: 1(0,0)
  round 1.5 hole 0.9: 2(0,2.54) 3(2.54,0) 4(2.54,2.54) 5(5.08,0) 6(5.08,2.54) 7(7.62,0) 8(7.62,2.54) 9(10.16,0) 10(10.16,2.54) 11(12.7,0) 12(12.7,2.54) 13(15.24,0) 14(15.24,2.54)
  silkscreen extent -1.27,-1.27 16.51,3.81, body extent -0.95,-1.21 16.55,3.78, height 9
HDR2X8_SMT [mil]
  rect 50x150 smd: 1(0,0) 2(0,215) 3(100,0) 4(100,215) 5(200,0) 6(200,215) 7(300,0) 8(300,215) 9(400,0) 10(400,215) 11(500,0) 12(500,215) 13(600,0) 14(600,215) 15(700,0) 16(700,215)
  silkscreen extent -51,-85 750,300, body extent -46,-47 746,253, height 246
HDR2X10 [mm]
  rect 1.5x1.5 hole 0.9: 1(0,0)
  round 1.5 hole 0.9: 2(0,2.54) 3(2.54,0) 4(2.54,2.54) 5(5.08,0) 6(5.08,2.54) 7(7.62,0) 8(7.62,2.54) 9(10.16,0) 10(10.16,2.54) 11(12.7,0) 12(12.7,2.54) 13(15.24,0) 14(15.24,2.54) 15(17.78,0) 16(17.78,2.54) 17(20.32,0) 18(20.32,2.54) 19(22.86,0) 20(22.86,2.54)
  silkscreen extent -1.27,-1.27 24.13,3.81, body extent -1.19,-1.16 23.99,3.74, height 9
HDR2X13_RA_CENTRONICS [mil] "Connector; IDC, Low Profile Male Header, Thru-Hole; 26 Position; Right Angle; Pitch 2.54 mm; Body 40.64 x 8.9 x 9.2 mm (LxWxH)"
  rect 82x82 hole 49.21: 1(-600,-100)
  round 82 hole 49.21: 2(-500,-100) 3(-400,-100) 4(-300,-100) 5(-200,-100) 6(-100,-100) 7(0,-100) 8(100,-100) 9(200,-100) 10(300,-100) 11(400,-100) 12(500,-100) 13(600,-100) 14(-600,0) 15(-500,0) 16(-400,0) 17(-300,0) 18(-200,0) 19(-100,0) 20(0,0) 21(100,0) 22(200,0) 23(300,0) 24(400,0) 25(500,0) 26(600,0)
  silkscreen extent -800,0 800,372, body extent -799,-120 810,376, height 315
HITACHI_TX09D50VM1CAA [mm]
  rect 2x0.3 smd: 1(-16.2,-28.4) 2(-16.2,-27.9) 3(-16.2,-27.4) 4(-16.2,-26.9) 5(-16.2,-26.4) 6(-16.2,-25.9) 7(-16.2,-25.4) 8(-16.2,-24.9) 9(-16.2,-24.4) 10(-16.2,-23.9) 11(-16.2,-23.4) 12(-16.2,-22.9) 13(-16.2,-22.4) 14(-16.2,-21.9) 15(-16.2,-21.4) 16(-16.2,-20.9) 17(-16.2,-20.4) 18(-16.2,-19.9) 19(-16.2,-19.4) 20(-16.2,-18.9) 21(-16.2,-18.4) 22(-16.2,-17.9) 23(-16.2,-17.4) 24(-16.2,-16.9) 25(-16.2,-16.4) 26(-16.2,-15.9) 27(-16.2,-15.4) 28(-16.2,-14.9) 29(-16.2,-14.4) 30(-16.2,-13.9) 31(-16.2,-13.4) 32(-16.2,-12.9) 33(-16.2,-12.4) 34(-16.2,-11.9) 35(-16.2,-11.4) 36(-16.2,-10.9) 37(-16.2,-10.4) 38(-16.2,-9.9) 39(-16.2,-9.4) 40(-16.2,-8.9) 41(-16.2,-8.4) 42(-16.2,-7.9) 43(-16.2,-7.4) 44(-16.2,-6.9) 45(-16.2,-6.4) 46(-16.2,-5.9) 47(-16.2,-5.4) 48(-16.2,-4.9) 49(-16.2,-4.4) 50(-16.2,-3.9)
  rect 1.4x1.2 smd: MH1(-13.175,-30.25) MH1(-13.175,-2.15)
  silkscreen extent -15.68,-30.25 1,-2.15, body extent -15.76,-30.33 -9.95,-2.14, height 1.5
INDP7575 [mm]
  rect 2.7x8 smd: 1(-2.7,0) 2(2.7,0)
  silkscreen extent -1.21,-3.74 1.18,3.73, body extent -3.71,-3.67 3.7,3.7, height 4.25
INDP182140 [mm]
  rect 3.8x3 smd: 1(-8.1,0) 2(8.1,0)
  silkscreen extent -8.5,-7.31 8.5,7.3, body extent -7.63,-5.4 7.6,5.47, height 7
IT-2175#1 [mm] "Switch, Push Button, Thru-Hole; 4 Leads; Body 8.5 x 8.5 mm (LxW typ); Row Spacing 9.0 mm; Pitch 4.5 mm"
  rect 1.65x1.65 hole 1: 1(-4.5,-2.25)
  round 1.65 hole 1: 2(4.5,-2.25) 3(-4.5,2.25) 4(4.5,2.25)
  silkscreen extent -4.25,-4.25 4.25,4.25, body extent -4.98,-4.37 4.98,4.33, height 4.5
IT-2175#2 [mm] "Switch, Push Button, Thru-Hole; 4 Leads; Body 8.5 x 8.5 mm (LxW typ); Row Spacing 9.0 mm; Pitch 4.5 mm"
  rect 1.65x1.65 hole 1: 1(-4.5,-2.25)
  round 1.65 hole 1: 2(-4.5,2.25) 3(4.5,-2.25) 4(4.5,2.25)
  silkscreen extent -4.25,-4.25 4.25,4.25, body extent -4.98,-4.37 4.98,4.33, height 4.5
KLD-0202 [mm]
  oval 2x4.5 hole 1 slot 3.5 at 90 deg: 1(13.7,0)
  oval 2x4 hole 1 slot 3 at 90 deg: 2(7.5,0)
  oval 4x2 hole 1 slot 3 at 0 deg: 3(10.5,-5)
  silkscreen extent 0,-4.5 13.7,4.5, body extent -0.26,-5.21 14.24,4.29, height 11
LCD_COVER [mm]
  round 1.1 hole 1.3 unplated: TFT_MOUNT(-33.2,-46) TFT_MOUNT(33.2,-46)
  round 2 hole 2.5 unplated: TFT_MOUNT(0,-92) TFT_MOUNT(0,0)
  Keep-Out Layer circle w0.4: c33.2,-46 r1.105
  Keep-Out Layer circle w0.4: c-33.2,-46 r1.105
  Keep-Out Layer circle w0.4: c0,-92 r2.154
  Keep-Out Layer circle w0.4: c0,0 r2.154
  silkscreen extent -33.8,-93.95 33.8,1.95
LEAD_FREE_S [mil]
  silkscreen extent -125,-125 125,125
Logo-Altium [mil]
  silkscreen extent -1025,-99 -556,102
MF_SM250 [mm] "PTC Resetatable Fuse"
  rect 2.3x4.6 smd: 1(-2.323,0.127) 2(6.077,0.127)
  silkscreen extent -4.12,-2.62 7.88,2.88, body extent -2.41,-2.27 6.2,2.51, height 1.7
MINIDIN6GREEN [mm]
  rect 1.6x1.6 hole 0.9: 1(8.45,-1.25)
  round 1.6 hole 0.9: 2(8.45,1.25) 3(8.45,-3.25) 4(8.45,3.25) 5(10.95,-3.25) 6(10.95,3.25)
  round 3.5 hole 2.3: MH1(4.7,0)
  oval 4.4x2.4 hole 0.9 slot 2.4 at 0 deg: MH2(5.45,6.905) MH3(5.45,-6.595)
  silkscreen extent -0.05,-7 12.7,7, body extent 0,-6.98 12.8,7.02, height 6.5
MINIDIN6PURPLE [mm]
  rect 1.6x1.6 hole 0.9: 1(8.45,-1.25)
  round 1.6 hole 0.9: 2(8.45,1.25) 3(8.45,-3.25) 4(8.45,3.25) 5(10.95,-3.25) 6(10.95,3.25)
  round 3.5 hole 2.3: MH1(4.7,0)
  oval 4.4x2.4 hole 0.9 slot 2.4 at 0 deg: MH2(5.45,6.905) MH3(5.45,-6.595)
  silkscreen extent -0.05,-7 12.7,7, body extent -0.1,-7.03 12.7,6.97, height 6.5
MOUNTING_HOLE_3MM [mm] "Non-plated mounting hole for 3mm screw"
  round 3.8 hole 3.4 mask+0.2: MOUNT(0,0)
  Top Layer circle w1: c0,0 r2.3
  Top Layer region: -2.8,-2.8 2.8,-2.8 2.8,2.8 -2.8,2.8
  Top Layer keep-out region: -3.3,-3.3 3.3,-3.3 3.3,3.3 -3.3,3.3
  Bottom Layer region: -2.8,-2.8 2.8,-2.8 2.8,2.8 -2.8,2.8
  Bottom Layer keep-out region: -3.3,-3.3 3.3,-3.3 3.3,3.3 -3.3,3.3
  Keep-Out Layer circle w1: c0,0 r2
"NANOBOARD LOGO" [mil]
  silkscreen extent -442,-67 456,59
NETTIE-SMT2-8X8#1 [mil]
  rect 10x7.87 on Mid1 paste-4.33 mask-4.33: 1(-35.1,-0.24) 2(-27.22,-0.24)
NETTIE-SMT2-8X8#2 [mil]
  rect 15.75x7.87 smd paste-4.33 mask-4.33: 1(-35.08,-0.24) 2(-27.2,-0.24)
NETTIE-SMT2-16X11 [mm]
  rect 0.8x1.016 smd paste-0.5 mask-0.5: 1(-0.891,-0.7) 2(-0.6,-0.7)
NETTIE-SMT2-31X39 [mm]
  rect 1.6x1.27 smd paste+0 mask+0: 1(-1.691,0.006) 2(-0.691,0.006)
NETTIE-SMT2-31X51#1 [mm]
  rect 2x1.27 smd paste-0.5 mask+0: 1(-0.891,0.006) 2(0.409,0.006)
NETTIE-SMT2-31X51#2 [mm]
  rect 2x0.8 smd paste-0.5 mask-0.5: 1(-0.891,0.006) 2(0.409,0.006)
PERIPHERAL_BOARD_1SLOT#1 [mil] "Outline of 2-Slot Peripheral Board"
  Top Layer region: 2440.94,452.76 2366.14,527.56 2366.14,937.01 2440.94,1011.81
  Top Layer region: 2440.94,2216.54 2366.14,2291.34 2366.14,2940.94 2440.94,3015.75
  Top Layer region: 1712.6,3228.35 1787.4,3153.54 2153.54,3153.54 2228.35,3228.35
  Top Layer region: 0,452.76 74.8,527.56 74.8,937.01 0,1011.81
  Top Layer region: 0,2216.54 74.8,2291.34 74.8,2940.94 0,3015.75
  silkscreen extent 0,0 2441,3228
PERIPHERAL_BOARD_1SLOT#2 [mil] "Outline of 2-Slot Peripheral Board"
  Top Layer region: 728.35,3228.35 653.54,3153.54 287.4,3153.54 212.6,3228.35
  Top Layer region: 0,2216.54 74.8,2291.34 74.8,2940.94 0,3015.75
  Top Layer region: 0,452.76 74.8,527.56 74.8,937.01 0,1011.81
  Top Layer region: 1712.6,3228.35 1787.4,3153.54 2153.54,3153.54 2228.35,3228.35
  Top Layer region: 2440.94,2216.54 2366.14,2291.34 2366.14,2940.94 2440.94,3015.75
  Top Layer region: 2440.94,452.76 2366.14,527.56 2366.14,937.01 2440.94,1011.81
  silkscreen extent 0,0 2441,3228
PERIPHERAL_BOARD_2SLOT [mil] "Outline of 2-Slot Peripheral Board"
  Top Layer region: 4921.26,452.76 4846.46,527.56 4846.46,937.01 4921.26,1011.81
  Top Layer region: 4921.26,2216.54 4846.46,2291.34 4846.46,2940.94 4921.26,3015.75
  Top Layer region: 0,452.76 74.8,527.56 74.8,937.01 0,1011.81
  Top Layer region: 728.35,3228.35 653.54,3153.54 287.4,3153.54 212.6,3228.35
  silkscreen extent 0,0 4921,3228
POT-R0911G-A1 [mm]
  round 2 hole 1.1: 1(-2.5,0) 2(0,0) 3(2.5,0) 4(-2.5,-2.5) 5(0,-2.5) 6(2.5,-2.5)
  silkscreen extent -4.9,-22.3 4.5,2.3, body extent -5.74,-26.56 5.75,2.91, height 12.64
QFN50P800X800_HS-57 [mm] "Quad Flat No Lead; 56 Terminals; Body 8 x 8 mm; Pitch 0.5 mm, Punch Version"
  rrect50% 0.3x0.86 smd: 1(-3.25,-3.92) 2(-2.75,-3.92) 3(-2.25,-3.92) 4(-1.75,-3.92) 5(-1.25,-3.92) 6(-0.75,-3.92) 7(-0.25,-3.92) 8(0.25,-3.92) 9(0.75,-3.92) 10(1.25,-3.92) 11(1.75,-3.92) 12(2.25,-3.92) 13(2.75,-3.92) 14(3.25,-3.92) 29(3.25,3.92) 30(2.75,3.92) 31(2.25,3.92) 32(1.75,3.92) 33(1.25,3.92) 34(0.75,3.92) 35(0.25,3.92) 36(-0.25,3.92) 37(-0.75,3.92) 38(-1.25,3.92) 39(-1.75,3.92) 40(-2.25,3.92) 41(-2.75,3.92) 42(-3.25,3.92)
  rrect50% 0.86x0.3 smd: 15(3.92,-3.25) 16(3.92,-2.75) 17(3.92,-2.25) 18(3.92,-1.75) 19(3.92,-1.25) 20(3.92,-0.75) 21(3.92,-0.25) 22(3.92,0.25) 23(3.92,0.75) 24(3.92,1.25) 25(3.92,1.75) 26(3.92,2.25) 27(3.92,2.75) 28(3.92,3.25) 43(-3.92,3.25) 44(-3.92,2.75) 45(-3.92,2.25) 46(-3.92,1.75) 47(-3.92,1.25) 48(-3.92,0.75) 49(-3.92,0.25) 50(-3.92,-0.25) 51(-3.92,-0.75) 52(-3.92,-1.25) 53(-3.92,-1.75) 54(-3.92,-2.25) 55(-3.92,-2.75) 56(-3.92,-3.25)
  Top Layer region: -2.75,-2.75 2.75,-2.75 2.75,2.75 -2.75,2.75
  silkscreen extent -4.05,-4.83 4.05,4.05, body extent -4.32,-4.24 4.26,4.28, height 0.55
QSOP65P600-20 [mil]
  rect 15x75 smd: 1(0,0) 2(25,0) 3(50,0) 4(75,0) 5(100,0) 6(125,0) 7(150,0) 8(175,0) 9(200,0) 10(225,0) 11(225,205) 12(200,205) 13(175,205) 14(150,205) 15(125,205) 16(100,205) 17(75,205) 18(50,205) 19(25,205) 20(0,205)
  silkscreen extent -38,6 240,146, body extent -15,-5 240,210, height 29
RESC1005-STAR [mm] "Chip Inductor 1005"
  rect 0.575x0.6 smd: 1(-0.538,0) 2(0.538,0)
  silkscreen extent -0.05,-0.38 0.05,0.38, body extent -0.71,-0.25 0.72,0.26, height 0.25
RESC3216 [mm]
  rect 1.6x1.8 smd: 1(-1.4,0) 2(1.4,0)
  silkscreen extent -0.3,-0.8 0.3,0.8, body extent -1.33,-0.81 1.37,0.85, height 0.55
SC70_6L [mm]
  rect 0.4x0.85 smd: 1(0,0) 2(0.65,0) 3(1.3,0) 4(1.3,1.85) 5(0.65,1.85) 6(0,1.85)
  silkscreen extent -0.8,-0.55 1.8,1.85, body extent -0.43,-0.38 1.73,2.22, height 0.64
SD_CARD_HRS_609_0003_5 [mm] "Hirose Secure Digital Card SMT Reverse"
  rect 1.25x2.5 smd: 1(-6.875,1.25) 2(-4.47,1.25) 3(-1.875,1.25) 4(0.625,1.25) 5(3.125,1.25) 6(5.625,1.25) 7(8.05,1.25) 8(9.75,1.25) 9(-9.47,1.25)
  rect 0.8x2.5 smd: CD(11.2,1.25)
  rect 1.4x2.5 smd: COM(12.8,1.25)
  oval 1.8x3 hole 0.8 slot 2 at 90 deg: S1(-14.25,-28.25)
  oval 1.9x2.6 hole 0.8 slot 1.5 at 90 deg: S2(13,-28.48)
  oval 2.3x1.8 hole 0.8 slot 1.3 at 0 deg: S3(-12.57,0.8) S6(11.23,-1.4)
  oval 1.4x1.9 hole 0.8 slot 1.3 at 90 deg: S4(-5.62,-1.05) S5(2.03,-1.05)
  rect 2.2x3.5 smd: WP(13,-25.23)
  Top Layer region: 9.975,-21.125 14.114,-21.125 14.114,-27 9.975,-27
  silkscreen extent -14.25,-26.8 13.5,-0.1, body extent -14.36,-28.3 13.84,2.1, height 2.9
SOIC8-200-BODY [mm] "SOIC (JEDEC) 8 PIN, 200 mils body width"
  rect 0.7x2.2 smd: 1(0,0) 2(1.27,0) 3(2.54,0) 4(3.81,0) 5(3.81,7) 6(2.54,7) 7(1.27,7) 8(0,7)
  silkscreen extent -1.34,0.54 4.4,5.4, body extent -0.61,0.06 4.47,7.1, height 1
SOIC127P600-16 [mm]
  rect 0.7x1.8 smd: 1(-4.445,-2.85) 2(-3.175,-2.85) 3(-1.905,-2.85) 4(-0.635,-2.85) 5(0.635,-2.85) 6(1.905,-2.85) 7(3.175,-2.85) 8(4.445,-2.85) 9(4.445,2.85) 10(3.175,2.85) 11(1.905,2.85) 12(0.635,2.85) 13(-0.635,2.85) 14(-1.905,2.85) 15(-3.175,2.85) 16(-4.445,2.85)
  silkscreen extent -5.42,-2.72 5,1.1, body extent -5,-2.93 4.95,2.93, height 1
SOP63P602-16 [mil]
  rect 82x16 smd: 1(-116,87.5) 2(-116,62) 3(-116,37.5) 4(-116,12.5) 5(-116,-12.5) 6(-116,-37.5) 7(-116,-62.5) 8(-116,-87.5) 9(116,-87.5) 10(116,-62.5) 11(116,-37.5) 12(116,-12.5) 13(116,12.5) 14(116,37.5) 15(116,62.5) 16(116,87.5)
  silkscreen extent -100,-100 60,125, body extent -107,-100 108,103, height 29
SOP127P600-8 [mm]
  rect 0.6x2.2 smd: 1(-1.905,-2.6) 2(-0.635,-2.6) 3(0.635,-2.6) 4(1.905,-2.6) 5(1.905,2.6) 6(0.635,2.6) 7(-0.635,2.6) 8(-1.905,2.6)
  silkscreen extent -2.88,-2.72 2.5,1.1, body extent -2.45,-2.76 2.39,2.98, height 1
SOT65P280-8 [mm]
  rect 1.5x0.35 smd: 1(-1.5,0.975) 2(-1.5,0.325) 3(-1.5,-0.325) 4(-1.5,-0.975) 5(1.5,-0.975) 6(1.5,-0.325) 7(1.5,0.325) 8(1.5,0.975)
  silkscreen extent -0.55,-1.3 0.55,1.3, body extent -1.58,-1.26 1.6,1.28, height 0.8
SOT95P230-3C [mm] "SOT23, 1=bottom-left, 2=bottom-right, 3=top"
  rect 0.9x0.95 smd: 1(-0.95,-1.25) 2(0.95,-1.25) 3(0,1.25)
  silkscreen extent -1.3,-0.38 1.3,1.25, body extent -1.14,-1.18 1.17,1.44, height 0.38
SOT95P230-3D [mm] "SOT23, 1=bottom-left, 2=top, 3=bottom-right"
  rect 0.9x0.95 smd: 1(-0.95,-1.25) 2(0,1.25) 3(0.95,-1.25)
  silkscreen extent -1.3,-0.38 1.3,1.25, body extent -1.14,-1.25 1.17,1.36, height 0.38
SOT95P284-5 [mm]
  rect 0.55x1.45 smd: 1(-0.95,-1.075) 2(0,-1.075) 3(0.95,-1.075) 4(0.95,1.075) 5(-0.95,1.075)
  silkscreen extent -1.67,-2.23 1.55,0.9, body extent -1.53,-1.46 1.5,1.54, height 0.8
SOT143 [mm] "SOT-143; 4 Leads; Body 3 x 2.6 mm, inc. leads (LxW max)"
  rect 1.35x1.35 smd: 1(-0.75,-1.1)
  rect 0.9x1.35 smd: 2(0.95,-1.1) 3(0.95,1.1) 4(-0.95,1.1)
  silkscreen extent -1.87,-2.22 1.75,0.7, body extent -1.52,-1.5 1.51,1.46, height 0.8
SOT-23-5 [mil] "SOT-23-5, 5-lead Small Outline Package (0.953mm pitch)"
  rect 27x39 smd: 1(0,0) 2(37.5,0) 3(75,0) 4(75,102) 5(0,102)
  silkscreen extent -30,30 105,85, body extent -22,-5 97,113, height 31
SSOP50P490-10 [mm] "Shrink Small Outline; 10 Leads; Body Width 3 mm; Pitch 0.5 mm"
  rect 0.3x1.6 smd: 1(-1,-2.05) 2(-0.5,-2.05) 3(0,-2.05) 4(0.5,-2.05) 5(1,-2.05) 6(1,2.05) 7(0.5,2.05) 8(0,2.05) 9(-0.5,2.05) 10(-1,2.05)
  silkscreen extent -1.82,-2.17 1.58,0.85, body extent -1.61,-1.97 1.62,1.93, height 0.8
STANDOFF_SOLDER_3MM [mm] "Non-plated hole for 3mm Soldered Standoff"
  round 6 / inner round 5 / far side round 5 hole 3.15 mask+0.1: STAND(0,0)
  Top Layer circle w1: c0,0 r2.2
  Top Layer keep-out circle w0.254: c0,0 r3.3
  Bottom Layer keep-out lines w0.4: -3.3,3.3 3.3,3.3 3.3,-3.3 -3.3,-3.3 -3.3,3.3
  Keep-Out Layer circle w0.6: c0,0 r2.2
  body extent -1.51,-1.51 1.51,1.51, height 9
SW_DTSM-61NT/R [mm] "Switch, Push Button, Thru-Hole; 4 Leads; Body 8.5 x 8.5 mm (LxW typ); Row Spacing 9.0 mm; Pitch 4.5 mm"
  rect 1.6x1.4 smd: 1(4.01,-2.25) 2(-4,-2.25) 3(4.01,2.24) 4(-4,2.24)
  silkscreen extent -3.16,-3.16 3.15,3.15, body extent -4.5,-3.1 4.5,3.1, height 4.5
T8019L-TNQ [mm]
  round 3.048 hole 1.5: 1(0,20.142) 2(0,23.952) 3(0,27.762)
  oval 2.7x3.81 hole 1.6: S1(2.54,7.442) S2(-2.54,7.442)
  silkscreen extent -3.43,0 3.43,26.11, body extent -3.5,-8.38 3.5,28.01, height 13
TestPin#1 [mil]
  round 70 hole 39.37: 1(0,0)
  silkscreen extent -41,-39 156,39
TestPin#2 [mil]
  round 60 hole 35.43: 1(0,0)
  silkscreen extent -41,-39 156,39
TestPin#3 [mil]
  round 60 hole 31.5: 1(-0.02,0.01)
  silkscreen extent -41,-39 156,39
TO254P1435-4 [mm]
  rect 1.6x3.6 smd: 1(0,0) 2(2.54,0) 3(5.08,0)
  rect 10.8x6.99 smd mask-1.25: 4(2.54,10.45)
  silkscreen extent -3.1,-0.13 8.2,15.4, body extent -3.01,-0.19 7.93,14.97, height 4
TO-263 [mm]
  rect 1x3.4 smd: 1(-3.4,0) 2(-1.7,0) 3(0,0) 4(1.7,0) 5(3.4,0)
  silkscreen extent -6,-2 6,16, body extent -5.14,-0.56 5.44,15.69, height 4
TRIM_3314J-1-203E [mm]
  rect 2x1.3 smd: 1(-2,-1.15) 3(-2,1.15)
  rrect50% 2x2 smd: 2(2,0)
  silkscreen extent -2.5,-2.5 2.5,2.5, body extent -2.43,-2.33 2.6,2.33, height 2
TS2.54X10 [mm] "10 way 2.54mm Pitch screw terminal"
  round 1.85 hole 1.1: 1(0,0) 2(0,-2.54) 3(0,-5.08) 4(0,-7.62) 5(0,-10.16) 6(0,-12.7) 7(0,-15.24) 8(0,-17.78) 9(0,-20.32) 10(0,-22.86)
  silkscreen extent -3.2,-24.38 3.25,1.52, body extent -3.1,-24.36 3.1,1.5, height 8.5
TSH-3675 [mm]
  oval 3x1.6 hole 0.6 slot 2 at 0 deg: 1(-0.2,3.85) 2(6.3,-3.85)
  oval 2.5x1.6 hole 0.6 slot 1.5 at 0 deg: 3(6,3.85) 10(1.9,-3.85) 11(3.1,3.85)
  round 1.3 hole 1.6 unplated: 12(6,0) 13(0,0)
  silkscreen extent -6,-4.75 9,4.75, body extent -6.15,-4.67 8.85,4.83, height 5
TSOC6 [mil]
  rect 25x71 smd: 1(-50,-75) 2(0,-75) 3(50,-75) 4(50,75) 5(0,75) 6(-50,75)
  silkscreen extent -115,-80 85,80, body extent -79,-90 84,91, height 40
TSOP65P638-16 [mm]
  rect 0.3x1.65 smd: 1(-2.275,-2.775) 2(-1.625,-2.775) 3(-0.975,-2.775) 4(-0.325,-2.775) 5(0.325,-2.775) 6(0.975,-2.775) 7(1.625,-2.775) 8(2.275,-2.775) 9(2.275,2.775) 10(1.625,2.775) 11(0.975,2.775) 12(0.325,2.775) 13(-0.325,2.775) 14(-0.975,2.775) 15(-1.625,2.775) 16(-2.275,2.775)
  silkscreen extent -3.1,-2.9 2.55,1.55, body extent -2.42,-2.59 2.56,2.65, height 0.8
TSOP65P640_HS-28 [mm]
  rect 0.36x1.78 smd: 1(0,0) 2(0.65,0) 3(1.3,0) 4(1.95,0) 5(2.6,0) 6(3.25,0) 7(3.9,0) 8(4.55,0) 9(5.2,0) 10(5.85,0) 11(6.5,0) 12(7.15,0) 13(7.8,0) 14(8.45,0) 15(8.45,5.9) 16(7.8,5.9) 17(7.15,5.9) 18(6.5,5.9) 19(5.85,5.9) 20(5.2,5.9) 21(4.55,5.9) 22(3.9,5.9) 23(3.25,5.9) 24(2.6,5.9) 25(1.95,5.9) 26(1.3,5.9) 27(0.65,5.9) 28(0,5.9)
  Top Layer region: -0.25,4.75 8.65,4.75 8.65,1.15 -0.25,1.15
  silkscreen extent -0.82,-0.12 8.9,4.83, body extent -0.32,0.14 8.64,5.76, height 0.8
TSOP80P1176-44 [mm]
  rect 0.5x1.4 smd: 1(-8.4,-5.7) 2(-7.6,-5.7) 3(-6.8,-5.7) 4(-6,-5.7) 5(-5.2,-5.7) 6(-4.4,-5.7) 7(-3.6,-5.7) 8(-2.8,-5.7) 9(-2,-5.7) 10(-1.2,-5.7) 11(-0.4,-5.7) 12(0.4,-5.7) 13(1.2,-5.7) 14(2,-5.7) 15(2.8,-5.7) 16(3.6,-5.7) 17(4.4,-5.7) 18(5.2,-5.7) 19(6,-5.7) 20(6.8,-5.7) 21(7.6,-5.7) 22(8.4,-5.7) 23(8.4,5.7) 24(7.6,5.7) 25(6.8,5.7) 26(6,5.7) 27(5.2,5.7) 28(4.4,5.7) 29(3.6,5.7) 30(2.8,5.7) 31(2,5.7) 32(1.2,5.7) 33(0.4,5.7) 34(-0.4,5.7) 35(-1.2,5.7) 36(-2,5.7) 37(-2.8,5.7) 38(-3.6,5.7) 39(-4.4,5.7) 40(-5.2,5.7) 41(-6,5.7) 42(-6.8,5.7) 43(-7.6,5.7) 44(-8.4,5.7)
  silkscreen extent -9.29,-5.7 9.26,4.45, body extent -9.24,-5.95 9.26,5.84, height 1
TSOP80P1176-54 [mm] "Plastic Small Outline; 54 Leads; Body Width 10.16 mm"
  rect 0.5x1.4 smd: 1(-10.4,-5.7) 2(-9.6,-5.7) 3(-8.8,-5.7) 4(-8,-5.7) 5(-7.2,-5.7) 6(-6.4,-5.7) 7(-5.6,-5.7) 8(-4.8,-5.7) 9(-4,-5.7) 10(-3.2,-5.7) 11(-2.4,-5.7) 12(-1.6,-5.7) 13(-0.8,-5.7) 14(0,-5.7) 15(0.8,-5.7) 16(1.6,-5.7) 17(2.4,-5.7) 18(3.2,-5.7) 19(4,-5.7) 20(4.8,-5.7) 21(5.6,-5.7) 22(6.4,-5.7) 23(7.2,-5.7) 24(8,-5.7) 25(8.8,-5.7) 26(9.6,-5.7) 27(10.4,-5.7) 28(10.4,5.7) 29(9.6,5.7) 30(8.8,5.7) 31(8,5.7) 32(7.2,5.7) 33(6.4,5.7) 34(5.6,5.7) 35(4.8,5.7) 36(4,5.7) 37(3.2,5.7) 38(2.4,5.7) 39(1.6,5.7) 40(0.8,5.7) 41(0,5.7) 42(-0.8,5.7) 43(-1.6,5.7) 44(-2.4,5.7) 45(-3.2,5.7) 46(-4,5.7) 47(-4.8,5.7) 48(-5.6,5.7) 49(-6.4,5.7) 50(-7.2,5.7) 51(-8,5.7) 52(-8.8,5.7) 53(-9.6,5.7) 54(-10.4,5.7)
  silkscreen extent -11.34,-5.67 11.15,4.4, body extent -11.23,-5.96 11.19,5.97, height 1
TSOP95P275-6 [mm]
  rect 0.7x1 smd: 1(-0.95,-1.2) 2(0,-1.2) 3(0.95,-1.2) 4(0.95,1.2) 5(0,1.2) 6(-0.95,1.2)
  silkscreen extent -1.87,-1.33 1.5,0.7, body extent -1.49,-1.3 1.51,1.3, height 0.8
TSSOP50P490-10 [mm]
  rect 1.5x0.25 smd: 1(-2.5,1) 2(-2.5,0.5) 3(-2.5,0) 4(-2.5,-0.5) 5(-2.5,-1) 6(2.5,-1) 7(2.5,-0.5) 8(2.5,0) 9(2.5,0.5) 10(2.5,1)
  silkscreen extent -1.5,-1.4 1.5,1.4, body extent -2.68,-1.41 2.78,1.43, height 0.9
"XTAL QSC26 QSMC-200S COMBI" [mm] "XTAL MC-306"
  rect 1.9x1.3 smd: 0(-1.615,-6.515) 0(1.615,-6.515) 1(-1.615,-1.015) 2(1.615,-1.015)
  silkscreen extent -1.9,-7.75 1.9,0.25, body extent -2.4,-7.77 2.47,0.25, height 1.7
XTAL-200X126-4 [mil] "CRYSTAL SMD 200x126x44 mils, 4 pads"
  rect 63x55 smd: 1(-81.5,-47.5) 2(81.5,-47.5) 3(81.5,47.5) 4(-81.5,47.5)
  silkscreen extent -31,-72 31,72, body extent -114,-73 113,73, height 39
